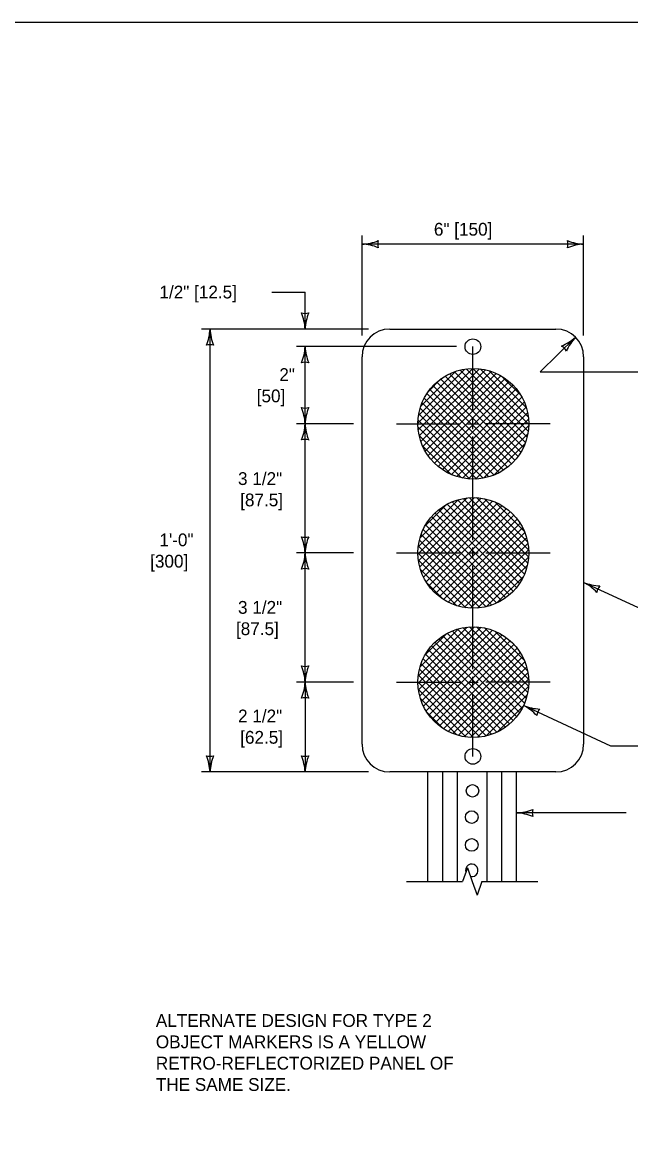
# Model space of a CAD drawing. Extents: x 49991.4 to 50021, y 49987.6 to 50011.4.
# Drawn here: x 50004.88 to 50007.73, y 49993.79 to 49999 of the extents above; entities that cross this region are included whole.
import ezdxf

# ---------------------------------------------------------------- set-up
doc = ezdxf.new("R2010")
doc.units = 0
for name, color, linetype in [('Level 1', 7, 'Continuous'), ('Level 2', 7, 'Continuous'), ('Level 3', 7, 'Continuous'), ('Level 5', 7, 'Continuous'), ('Level 6', 7, 'Continuous')]:
    doc.layers.add(name, color=color, linetype=linetype)

msp = doc.modelspace()

# ---------------------------------------------------------------- linework, layer by layer
at = {"layer": 'Level 1'}
for p, q in [((50006.6021, 49997.5609), (50007.3807, 49997.5609)), ((50006.4724, 49995.6151), (50006.4724, 49997.4312)), ((50007.5104, 49997.4312), (50007.5104, 49995.6151)), ((50006.7342, 49997.1201), (50006.9906, 49997.3765)), ((50006.7358, 49997.0885), (50007.0222, 49997.375)), ((50006.7372, 49997.1564), (50006.9544, 49997.3736)), ((50006.7406, 49997.06), (50007.0507, 49997.3702)), ((50006.7479, 49997.2003), (50006.9105, 49997.3629)), ((50006.7479, 49997.0342), (50007.0767, 49997.3629)), ((50007.2378, 49997.0295), (50006.906, 49997.3613)), ((50007.2455, 49997.055), (50006.9316, 49997.369)), ((50007.2508, 49997.083), (50006.9595, 49997.3743)), ((50007.253, 49997.114), (50006.9905, 49997.3765)), ((50007.251, 49997.1493), (50007.0257, 49997.3746)), ((50007.2422, 49997.1913), (50007.0678, 49997.3657)), ((50006.7573, 49997.0103), (50007.1005, 49997.3535)), ((50006.7685, 49996.9883), (50007.1225, 49997.3423)), ((50006.7814, 49996.9679), (50007.1428, 49997.3293)), ((50006.7833, 49997.269), (50006.8417, 49997.3274)), ((50006.7959, 49996.9492), (50007.1615, 49997.3148)), ((50007.1885, 49996.9459), (50006.8223, 49997.312)), ((50007.2032, 49996.9644), (50006.8408, 49997.3268)), ((50007.2164, 49996.9844), (50006.8609, 49997.34)), ((50007.228, 49997.006), (50006.8825, 49997.3516)), ((50007.216, 49997.2507), (50007.1272, 49997.3395)), ((50007.135, 49996.8996), (50006.7761, 49997.2586)), ((50007.1543, 49996.9136), (50006.79, 49997.2778)), ((50007.1721, 49996.929), (50006.8054, 49997.2957)), ((50006.812, 49996.932), (50007.1787, 49997.2988)), ((50006.8295, 49996.9163), (50007.1944, 49997.2813)), ((50006.8485, 49996.9021), (50007.2086, 49997.2622)), ((50007.0913, 49996.8769), (50006.7533, 49997.2149)), ((50007.114, 49996.8874), (50006.7638, 49997.2376)), ((50006.8692, 49996.8895), (50007.2212, 49997.2416)), ((50006.8916, 49996.8787), (50007.2321, 49997.2192)), ((50007.0398, 49996.8619), (50006.7384, 49997.1633)), ((50007.0667, 49996.8682), (50006.7447, 49997.1902)), ((50006.9158, 49996.8697), (50007.2411, 49997.195)), ((50006.9422, 49996.8629), (50007.2479, 49997.1686)), ((50007.0102, 49996.8583), (50006.7347, 49997.1338)), ((50006.9769, 49996.8583), (50006.7347, 49997.1006)), ((50006.9713, 49996.8587), (50007.252, 49997.1395)), ((50007.0037, 49996.8579), (50007.2528, 49997.107)), ((50006.9383, 49996.8637), (50006.7402, 49997.0618)), ((50007.0413, 49996.8622), (50007.2486, 49997.0696)), ((50006.889, 49996.8798), (50006.7563, 49997.0124)), ((50007.0877, 49996.8754), (50007.2353, 49997.023)), ((50006.7343, 49996.5057), (50006.9998, 49996.7712)), ((50006.7358, 49996.5404), (50006.9651, 49996.7697)), ((50006.7369, 49996.475), (50007.0305, 49996.7686)), ((50006.7424, 49996.4473), (50007.0582, 49996.7631)), ((50006.7437, 49996.5815), (50006.924, 49996.7618)), ((50006.7503, 49996.422), (50007.0836, 49996.7552)), ((50006.7602, 49996.3986), (50007.1069, 49996.7453)), ((50006.7669, 49996.6379), (50006.8674, 49996.7385)), ((50006.7719, 49996.3771), (50007.1283, 49996.7335)), ((50007.2226, 49996.3901), (50006.8718, 49996.7409)), ((50007.2333, 49996.4126), (50006.8944, 49996.7515)), ((50007.242, 49996.4371), (50006.9188, 49996.7603)), ((50007.2485, 49996.4638), (50006.9455, 49996.7668)), ((50007.2523, 49996.4933), (50006.9749, 49996.7706)), ((50007.2526, 49996.5262), (50007.0079, 49996.7709)), ((50007.2477, 49996.5643), (50007.0462, 49996.7659)), ((50007.2326, 49996.6127), (50007.0944, 49996.7509)), ((50006.7853, 49996.3572), (50007.1483, 49996.7202)), ((50007.1637, 49996.316), (50006.7977, 49996.682)), ((50006.8003, 49996.339), (50007.1665, 49996.7052)), ((50007.1807, 49996.3322), (50006.8139, 49996.699)), ((50006.8167, 49996.3221), (50007.1833, 49996.6888)), ((50007.1963, 49996.3499), (50006.8317, 49996.7145)), ((50007.2102, 49996.3692), (50006.8509, 49996.7285)), ((50007.125, 49996.2882), (50006.7699, 49996.6433)), ((50007.1451, 49996.3014), (50006.783, 49996.6634)), ((50006.8346, 49996.3069), (50007.1986, 49996.6708)), ((50006.8542, 49996.2932), (50007.2123, 49996.6513)), ((50006.8753, 49996.2811), (50007.2245, 49996.6302)), ((50007.0796, 49996.2671), (50006.7489, 49996.5978)), ((50007.1032, 49996.2768), (50006.7585, 49996.6215)), ((50006.8982, 49996.2707), (50007.2348, 49996.6074)), ((50006.923, 49996.2623), (50007.2432, 49996.5825)), ((50007.0258, 49996.2545), (50006.7362, 49996.5441)), ((50007.054, 49996.2596), (50006.7413, 49996.5722)), ((50006.9501, 49996.2562), (50007.2493, 49996.5554)), ((50006.98, 49996.2528), (50007.2527, 49996.5256)), ((50006.9945, 49996.2525), (50006.7342, 49996.5128)), ((50006.959, 49996.2548), (50006.7365, 49996.4773)), ((50007.0137, 49996.2533), (50007.2522, 49996.4918)), ((50006.9163, 49996.2643), (50006.746, 49996.4346)), ((50007.053, 49996.2594), (50007.2461, 49996.4525)), ((50006.8541, 49996.2932), (50006.7747, 49996.3727)), ((50007.1041, 49996.2772), (50007.2283, 49996.4014)), ((50006.7343, 49995.9002), (50006.9998, 49996.1657)), ((50006.7358, 49995.9349), (50006.9652, 49996.1643)), ((50006.7369, 49995.8695), (50007.0306, 49996.1632)), ((50007.2483, 49995.8585), (50006.9455, 49996.1613)), ((50007.2523, 49995.8878), (50006.9749, 49996.1651)), ((50007.2526, 49995.9207), (50007.0079, 49996.1654)), ((50007.2477, 49995.9588), (50007.0462, 49996.1604)), ((50006.7424, 49995.8418), (50007.0582, 49996.1576)), ((50006.7437, 49995.976), (50006.924, 49996.1563)), ((50006.7503, 49995.8165), (50007.0836, 49996.1497)), ((50006.7602, 49995.7931), (50007.1069, 49996.1398)), ((50006.7668, 49996.0323), (50006.8675, 49996.1331)), ((50006.772, 49995.7717), (50007.1284, 49996.1281)), ((50006.7854, 49995.7518), (50007.1483, 49996.1147)), ((50007.1962, 49995.7445), (50006.8317, 49996.109)), ((50007.2102, 49995.7637), (50006.8509, 49996.123)), ((50007.2226, 49995.7846), (50006.8718, 49996.1354)), ((50007.2332, 49995.8072), (50006.8943, 49996.1461)), ((50007.2418, 49995.8318), (50006.9188, 49996.1548)), ((50007.2327, 49996.0071), (50007.0943, 49996.1455)), ((50007.145, 49995.696), (50006.783, 49996.0579)), ((50007.1636, 49995.7106), (50006.7977, 49996.0765)), ((50006.8003, 49995.7335), (50007.1666, 49996.0998)), ((50007.1806, 49995.7268), (50006.8139, 49996.0935)), ((50006.8168, 49995.7167), (50007.1833, 49996.0833)), ((50006.8346, 49995.7014), (50007.1986, 49996.0653)), ((50007.103, 49995.6715), (50006.7585, 49996.016)), ((50007.1248, 49995.6829), (50006.7699, 49996.0378)), ((50006.8542, 49995.6877), (50007.2124, 49996.0459)), ((50006.8753, 49995.6756), (50007.2245, 49996.0247)), ((50007.0539, 49995.6542), (50006.7413, 49995.9667)), ((50007.0794, 49995.6618), (50006.7489, 49995.9923)), ((50006.8982, 49995.6652), (50007.2348, 49996.0019)), ((50006.923, 49995.6568), (50007.2432, 49995.977)), ((50006.9945, 49995.647), (50006.7342, 49995.9073)), ((50007.0258, 49995.649), (50006.7362, 49995.9386)), ((50006.9501, 49995.6507), (50007.2493, 49995.9499)), ((50006.9801, 49995.6474), (50007.2527, 49995.9201)), ((50006.959, 49995.6493), (50006.7365, 49995.8718)), ((50007.0137, 49995.6478), (50007.2521, 49995.8862)), ((50007.0531, 49995.654), (50007.246, 49995.8469)), ((50006.9163, 49995.6588), (50006.746, 49995.8291)), ((50007.1045, 49995.6721), (50007.2283, 49995.7959)), ((50006.854, 49995.6878), (50006.7748, 49995.7671)), ((50007.3807, 49995.4854), (50006.6021, 49995.4854)), ((50006.781, 49994.9715), (50006.781, 49995.4854)), ((50006.8501, 49994.9715), (50006.8501, 49995.4854)), ((50006.9193, 49994.9715), (50006.9193, 49995.4854)), ((50007.0579, 49994.9715), (50007.0579, 49995.4854)), ((50007.1271, 49994.9715), (50007.1271, 49995.4854)), ((50007.1961, 49994.9715), (50007.1961, 49995.4854))]:
    msp.add_line(p, q, dxfattribs=at)
msp.add_lwpolyline([(49999.3835, 49998.9992), (50016.7501, 49998.9992), (50016.7501, 49987.7988), (49999.3835, 49987.7988)], close=True, dxfattribs=at)
for centre, radius in [((50006.9914, 49997.4786), 0.0366), ((50006.9936, 49997.1172), 0.2594), ((50006.9936, 49996.5119), 0.2594), ((50006.9936, 49995.9064), 0.2594), ((50006.9914, 49995.5583), 0.0366), ((50006.9899, 49995.3969), 0.0293), ((50006.9862, 49995.2738), 0.0293), ((50006.9862, 49995.1434), 0.0293)]:
    msp.add_circle(centre, radius, dxfattribs=at)
for centre, radius, start, end in [((50006.6021, 49997.4312), 0.1297, 90, 180), ((50007.3807, 49997.4312), 0.1297, 0, 90), ((50006.6021, 49995.6151), 0.1297, 180, 270), ((50007.3807, 49995.6151), 0.1297, 270, 0), ((50006.9862, 49995.0241), 0.0293, 258.0601, 198.9096)]:
    msp.add_arc(centre, radius, start, end, dxfattribs=at)
at = {"layer": 'Level 3'}
for p, q in [((50006.4724, 49997.5312), (50006.4724, 49997.9989)), ((50007.5104, 49997.5312), (50007.5104, 49997.9989)), ((50007.5104, 49997.9589), (50006.4724, 49997.9589)), ((50006.0493, 49997.7346), (50006.2055, 49997.7346)), ((50006.2055, 49997.5609), (50006.2055, 49997.7346)), ((50006.5021, 49997.5609), (50005.72, 49997.5609)), ((50005.76, 49995.4854), (50005.76, 49997.5609)), ((50007.4724, 49997.5229), (50007.3064, 49997.36)), ((50006.9148, 49997.4786), (50006.1655, 49997.4786)), ((50006.2055, 49997.1172), (50006.2055, 49997.4786)), ((50007.3064, 49997.36), (50007.7874, 49997.36)), ((50006.4324, 49997.1172), (50006.1655, 49997.1172)), ((50006.2055, 49996.512), (50006.2055, 49997.1172)), ((50006.4324, 49996.5119), (50006.1655, 49996.5119)), ((50006.2055, 49995.9068), (50006.2055, 49996.512)), ((50007.8258, 49996.2274), (50007.5104, 49996.374)), ((50006.4324, 49995.9068), (50006.1655, 49995.9068)), ((50006.2055, 49995.9068), (50006.2055, 49995.4854)), ((50007.6379, 49995.6069), (50007.2288, 49995.7971)), ((50007.7874, 49995.6069), (50007.6379, 49995.6069)), ((50006.5021, 49995.4854), (50005.72, 49995.4854)), ((50007.7103, 49995.2932), (50007.1961, 49995.2932))]:
    msp.add_line(p, q, dxfattribs=at)
for centre, radius, start, end in [((50006.4609, 49998.1916), 0.233, 272.8273, 292.0772), ((50006.4632, 49997.7368), 0.2223, 67.456, 87.6395), ((50006.6006, 49997.9589), 0.0548, 162.1388, 197.8612), ((50007.5196, 49998.181), 0.2223, 247.456, 267.6395), ((50007.3822, 49997.9589), 0.0548, 342.1388, 17.8612), ((50007.5219, 49997.7262), 0.233, 92.8273, 112.0772), ((50006.2055, 49997.6891), 0.0548, 252.1388, 287.8612), ((50005.9728, 49997.5494), 0.233, 2.8273, 22.0772), ((50006.4276, 49997.5517), 0.2223, 157.456, 177.6395), ((50005.5379, 49997.5701), 0.2223, 337.456, 357.6395), ((50005.9927, 49997.5724), 0.233, 182.8273, 202.0772), ((50007.3234, 49997.6879), 0.2223, 291.916, 312.0995), ((50007.6436, 49997.3649), 0.233, 137.2873, 156.5372), ((50005.76, 49997.4327), 0.0548, 72.1388, 107.8612), ((50005.9834, 49997.4878), 0.2223, 337.456, 357.6395), ((50006.4382, 49997.4901), 0.233, 182.8273, 202.0772), ((50007.3809, 49997.4331), 0.0548, 26.5988, 62.3212), ((50006.2055, 49997.3504), 0.0548, 72.1388, 107.8612), ((50006.2055, 49997.2454), 0.0548, 252.1388, 287.8612), ((50005.9728, 49997.1057), 0.233, 2.8273, 22.0772), ((50006.4276, 49997.108), 0.2223, 157.456, 177.6395), ((50005.9834, 49997.1264), 0.2223, 337.456, 357.6395), ((50006.4382, 49997.1287), 0.233, 182.8273, 202.0772), ((50006.2055, 49996.989), 0.0548, 72.1388, 107.8612), ((50006.2055, 49996.6401), 0.0548, 252.1388, 287.8612), ((50005.9728, 49996.5004), 0.233, 2.8273, 22.0772), ((50006.4276, 49996.5027), 0.2223, 157.456, 177.6395), ((50005.9834, 49996.5211), 0.2223, 337.456, 357.6395), ((50006.4382, 49996.5234), 0.233, 182.8273, 202.0772), ((50006.2055, 49996.3837), 0.0548, 72.1388, 107.8612), ((50007.4085, 49996.1764), 0.2223, 42.5325, 62.716), ((50007.598, 49996.5899), 0.233, 247.9038, 267.1537), ((50007.6267, 49996.32), 0.0548, 137.2153, 172.9377), ((50006.2055, 49996.035), 0.0548, 252.1388, 287.8612), ((50005.9728, 49995.8953), 0.233, 2.8273, 22.0772), ((50006.4276, 49995.8976), 0.2223, 157.456, 177.6395), ((50005.9834, 49995.916), 0.2223, 337.456, 357.6395), ((50006.4382, 49995.9183), 0.233, 182.8273, 202.0772), ((50006.2055, 49995.7786), 0.0548, 72.1388, 107.8612), ((50007.1269, 49995.5995), 0.2223, 42.5212, 62.7047), ((50007.3165, 49996.0129), 0.233, 247.8925, 267.1424), ((50007.3451, 49995.743), 0.0548, 137.204, 172.9264), ((50005.76, 49995.6136), 0.0548, 252.1388, 287.8612), ((50005.5273, 49995.4739), 0.233, 2.8273, 22.0772), ((50005.9821, 49995.4762), 0.2223, 157.456, 177.6395), ((50006.2055, 49995.6136), 0.0548, 252.1388, 287.8612), ((50005.9728, 49995.4739), 0.233, 2.8273, 22.0772), ((50006.4276, 49995.4762), 0.2223, 157.456, 177.6395), ((50007.1846, 49995.5259), 0.233, 272.8273, 292.0772), ((50007.1869, 49995.0711), 0.2223, 67.456, 87.6395), ((50007.3243, 49995.2932), 0.0548, 162.1388, 197.8612)]:
    msp.add_arc(centre, radius, start, end, dxfattribs=at)
at = {"layer": 'Level 5'}
for p, q in [((50006.9914, 49997.1773), (50006.9914, 49997.4786)), ((50006.6342, 49997.1172), (50006.9314, 49997.117)), ((50006.9664, 49997.1173), (50007.0164, 49997.1173)), ((50006.9914, 49997.0923), (50006.9914, 49997.1423)), ((50007.0514, 49997.118), (50007.353, 49997.1183)), ((50006.9914, 49996.572), (50006.9914, 49997.0573)), ((50006.9914, 49996.487), (50006.9914, 49996.537)), ((50006.6342, 49996.5119), (50006.931, 49996.5117)), ((50006.9664, 49996.512), (50007.0164, 49996.512)), ((50007.052, 49996.5119), (50007.353, 49996.5122)), ((50006.9914, 49995.9667), (50006.9914, 49996.452)), ((50006.6342, 49995.9068), (50006.9312, 49995.9069)), ((50006.9664, 49995.9067), (50007.0164, 49995.9067)), ((50006.9914, 49995.8817), (50006.9914, 49995.9317)), ((50007.0526, 49995.9074), (50007.353, 49995.9077)), ((50006.9914, 49995.5583), (50006.9914, 49995.8467))]:
    msp.add_line(p, q, dxfattribs=at)
at = {"layer": 'Level 6'}
for p, q in [((50006.9659, 49995.0355), (50006.9432, 49994.9715)), ((50006.9659, 49995.0355), (50006.9886, 49994.9715)), ((50006.681, 49994.9715), (50006.9432, 49994.9715)), ((50006.9886, 49994.9715), (50007.0113, 49994.9075)), ((50007.034, 49994.9715), (50007.0113, 49994.9075)), ((50007.034, 49994.9715), (50007.2961, 49994.9715))]:
    msp.add_line(p, q, dxfattribs=at)

# ---------------------------------------------------------------- texts
at = {"layer": 'Level 2'}
for s, p in [('6" [150]', (50006.8089, 49997.9989)), ('2"', (50006.0848, 49997.3177)), ('[50]', (50005.9789, 49997.2177)), ('2 1/2"', (50005.8914, 49995.7177)), ('[62.5]', (50005.9014, 49995.6177)), ('ALTERNATE DESIGN FOR TYPE 2 ', (50005.5062, 49994.2905)), ('OBJECT MARKERS IS A YELLOW ', (50005.5062, 49994.1905)), ('RETRO-REFLECTORIZED PANEL OF ', (50005.5062, 49994.0905)), ('THE SAME SIZE. ', (50005.5062, 49993.9905))]:
    msp.add_text(s, height=0.06, dxfattribs=at).set_placement(p)
for s, rotation, p in [('1/2" [12.5]', 0.0331, (50005.5232, 49997.7043)), ('3 1/2"', 0.0188, (50005.8913, 49996.8302)), ('[87.5]', 0.0188, (50005.9014, 49996.7302)), ('1\'-0"', 0.0847, (50005.5231, 49996.5429)), ('[300]', 0.0847, (50005.4797, 49996.4428)), ('3 1/2"', 0.0565, (50005.8913, 49996.2266)), (' [87.5]', 0.0565, (50005.8594, 49996.1266))]:
    msp.add_text(s, height=0.06, rotation=rotation, dxfattribs=at).set_placement(p)

doc.saveas('drawing.dxf')
